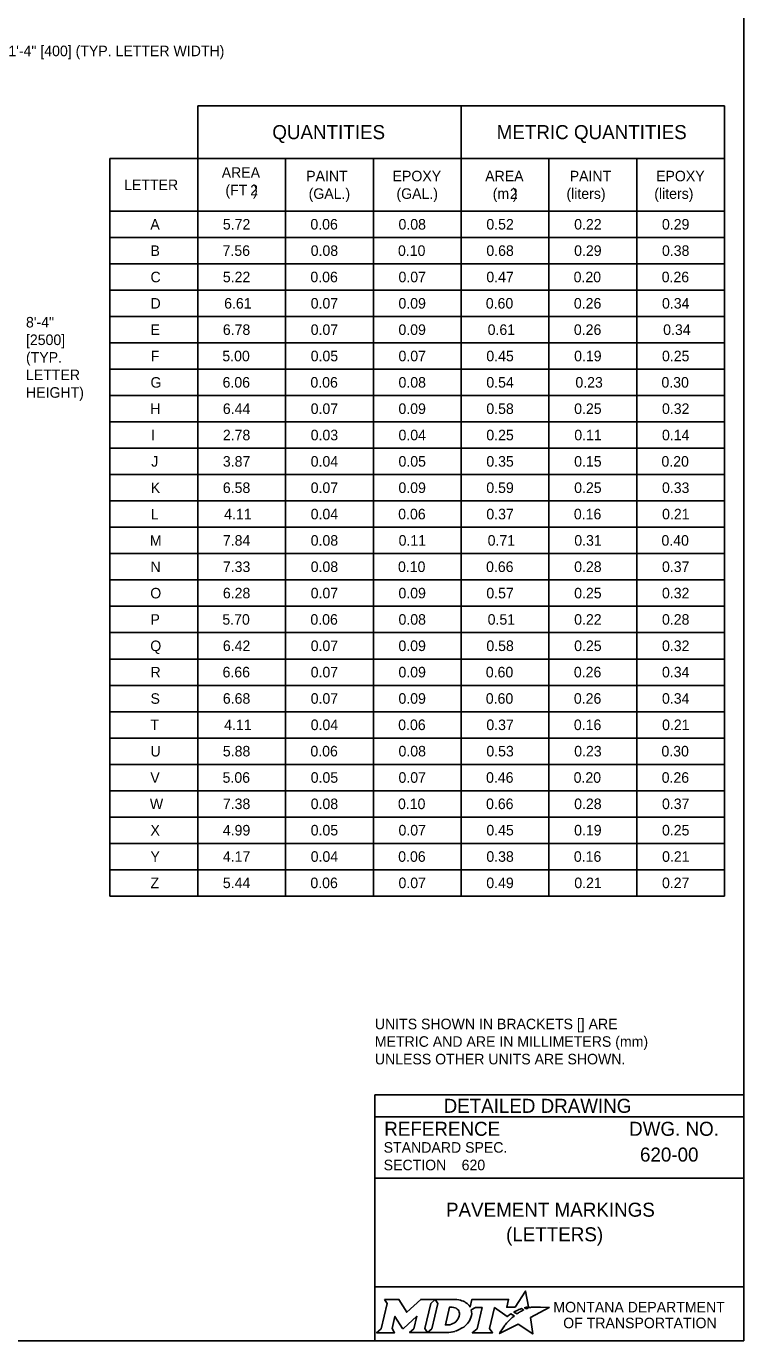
# Model space of a CAD drawing. Extents: x 49991.4 to 50021, y 49987.6 to 50011.4.
# Drawn here: x 50012.67 to 50016.75, y 49987.8 to 49995.28 of the extents above; entities that cross this region are included whole.
import ezdxf

# ---------------------------------------------------------------- set-up
doc = ezdxf.new("R2010")
doc.units = 0
for name, color, linetype in [('Default', 7, 'Continuous'), ('Level 1', 7, 'Continuous'), ('Level 2', 7, 'Continuous'), ('Level 5', 7, 'Continuous')]:
    doc.layers.add(name, color=color, linetype=linetype)

msp = doc.modelspace()

# ---------------------------------------------------------------- linework, layer by layer
at = {"layer": 'Default'}
for points in [[(50015.5126, 49987.9811), (50015.5023, 49987.9867), (50015.5139, 49987.9895), (50015.5255, 49987.9915), (50015.5081, 49988.0816), (50015.4486, 49987.9903), (50015.4013, 49987.9896), (50015.4116, 49988.0337), (50015.2024, 49988.0338), (50015.1923, 49987.9913), (50015.1865, 49987.9996)], [(50014.7056, 49988.0338), (50014.7197, 49988.0104), (50014.6862, 49987.8671), (50014.6605, 49987.8446), (50014.7621, 49987.8446), (50014.7486, 49987.8674), (50014.7648, 49987.9375), (50014.8085, 49987.8685), (50014.8138, 49987.8685), (50014.8889, 49987.938), (50014.8725, 49987.8669), (50014.8478, 49987.8449), (50014.9494, 49987.8449), (50014.9356, 49987.8682), (50014.9688, 49988.0106)], [(50014.9688, 49988.0106), (50014.9941, 49988.0338), (50014.9117, 49988.0338), (50014.8321, 49987.9608), (50014.7876, 49988.0335), (50014.7056, 49988.0338)], [(50015.1077, 49988.0338), (50014.9941, 49988.0338), (50015.0088, 49988.0109), (50014.9749, 49987.8671), (50014.9494, 49987.8449), (50015.06, 49987.8449)], [(50015.3882, 49987.8843), (50015.3729, 49987.8599), (50015.3682, 49987.8524), (50015.3624, 49987.8438), (50015.3601, 49987.8395), (50015.4654, 49987.8926), (50015.5493, 49987.8375), (50015.5362, 49987.9302), (50015.6431, 49987.9886), (50015.5938, 49987.9894), (50015.5637, 49987.9898), (50015.5429, 49987.9901), (50015.5361, 49987.9886), (50015.5312, 49987.9874), (50015.5228, 49987.9851), (50015.5126, 49987.9811)], [(50015.1317, 49987.9471), (50015.1305, 49987.939), (50015.1273, 49987.9297), (50015.1231, 49987.9215), (50015.1175, 49987.914), (50015.111, 49987.9071), (50015.1031, 49987.9008), (50015.0948, 49987.8961), (50015.0857, 49987.8922), (50015.0766, 49987.8899), (50015.0674, 49987.889), (50015.0515, 49987.889), (50015.0751, 49987.989), (50015.0911, 49987.989), (50015.0987, 49987.9884), (50015.1063, 49987.9865), (50015.1129, 49987.9835), (50015.119, 49987.9793), (50015.1238, 49987.9743), (50015.1275, 49987.9683), (50015.1302, 49987.9621), (50015.1318, 49987.9547), (50015.1318, 49987.9517), (50015.1317, 49987.9471)], [(50015.1991, 49987.9747), (50015.2237, 49987.9878), (50015.2606, 49987.9878), (50015.232, 49987.8673), (50015.2045, 49987.8446), (50015.3207, 49987.8446), (50015.3037, 49987.8675), (50015.3319, 49987.9877), (50015.4032, 49987.936), (50015.4243, 49987.9511), (50015.444, 49987.9402)], [(50015.4622, 49987.9535), (50015.4598, 49987.9518), (50015.4415, 49987.9614), (50015.4518, 49987.9671), (50015.4559, 49987.9693), (50015.4645, 49987.9733), (50015.4702, 49987.9759), (50015.4781, 49987.9789), (50015.4854, 49987.9816), (50015.4972, 49987.9742), (50015.4932, 49987.9721), (50015.4886, 49987.9696), (50015.4844, 49987.9674), (50015.4794, 49987.9645), (50015.4775, 49987.9634), (50015.4748, 49987.9618), (50015.4723, 49987.9604), (50015.47, 49987.9588), (50015.4674, 49987.957), (50015.4647, 49987.9552), (50015.4622, 49987.9535)], [(50015.1057, 49987.8522), (50015.1141, 49987.8548), (50015.1271, 49987.8602), (50015.1475, 49987.8712)], [(50015.4021, 49987.9004), (50015.4021, 49987.9004)]]:
    msp.add_lwpolyline(points, dxfattribs=at)
for centre, radius, start, end in [((50015.0868, 49987.9727), 0.1183, 300.91025, 339.13831), ((50015.1308, 49987.9554), 0.0709, 339.53292, 15.85821)]:
    msp.add_arc(centre, radius, start, end, dxfattribs=at)
for centre, major_axis, ratio, start_param, end_param in [((50015.1056, 49987.9864), (0.0834, -0.0037), 0.568097, 0.61298, 1.570796), ((50015.1612, 49987.9937), (0.0361, -0.0295), 0.469099, 1.225588, 1.570796), ((50015.4119, 49987.9106), (-0.0098, -0.0102), 0.016458, 3.141593, 6.279097), ((50015.4329, 49987.9305), (-0.0112, -0.0097), 0.021651, 3.157348, 6.283185), ((50015.0603, 49987.9932), (0, 0.1484), 0.987302, 3.139398, 3.456847), ((50015.3952, 49987.8923), (-0.00694, -0.00806), 0.008222, 0, 3.137361)]:
    msp.add_ellipse(centre, major_axis=major_axis, ratio=ratio, start_param=start_param, end_param=end_param, dxfattribs=at)
at = {"layer": 'Level 1'}
msp.add_lwpolyline([(49999.3835, 49998.9992), (50016.7501, 49998.9992), (50016.7501, 49987.7988), (49999.3835, 49987.7988)], close=True, dxfattribs=at)
at = {"layer": 'Level 2'}
for p, q in [((50013.6416, 49994.8304), (50013.6416, 49990.3304)), ((50013.6416, 49994.8304), (50016.6416, 49994.8304)), ((50015.1416, 49994.8304), (50015.1416, 49990.3304)), ((50016.6416, 49994.8304), (50016.6416, 49990.3304)), ((50013.1416, 49994.5304), (50016.6416, 49994.5304)), ((50013.1416, 49994.5304), (50013.1416, 49990.3304)), ((50014.1416, 49994.5304), (50014.1416, 49990.3304)), ((50014.6416, 49994.5304), (50014.6416, 49990.3304)), ((50015.6416, 49994.5304), (50015.6416, 49990.3304)), ((50016.1416, 49994.5304), (50016.1416, 49990.3304)), ((50013.1416, 49994.2304), (50016.6416, 49994.2304)), ((50013.1416, 49994.0804), (50016.6416, 49994.0804)), ((50013.1416, 49993.9304), (50016.6416, 49993.9304)), ((50013.1416, 49993.7804), (50016.6416, 49993.7804)), ((50013.1416, 49993.6304), (50016.6416, 49993.6304)), ((50013.1416, 49993.4804), (50016.6416, 49993.4804)), ((50013.1416, 49993.3304), (50016.6416, 49993.3304)), ((50013.1416, 49993.1804), (50016.6416, 49993.1804)), ((50013.1416, 49993.0304), (50016.6416, 49993.0304)), ((50013.1416, 49992.8804), (50016.6416, 49992.8804)), ((50013.1416, 49992.7304), (50016.6416, 49992.7304)), ((50013.1416, 49992.5804), (50016.6416, 49992.5804)), ((50013.1416, 49992.4304), (50016.6416, 49992.4304)), ((50013.1416, 49992.2804), (50016.6416, 49992.2804)), ((50013.1416, 49992.1304), (50016.6416, 49992.1304)), ((50013.1416, 49991.9804), (50016.6416, 49991.9804)), ((50013.1416, 49991.8304), (50016.6416, 49991.8304)), ((50013.1416, 49991.6804), (50016.6416, 49991.6804)), ((50013.1416, 49991.5304), (50016.6416, 49991.5304)), ((50013.1416, 49991.3804), (50016.6416, 49991.3804)), ((50013.1416, 49991.2304), (50016.6416, 49991.2304)), ((50013.1416, 49991.0804), (50016.6416, 49991.0804)), ((50013.1416, 49990.9304), (50016.6416, 49990.9304)), ((50013.1416, 49990.7804), (50016.6416, 49990.7804)), ((50013.1416, 49990.6304), (50016.6416, 49990.6304)), ((50013.1416, 49990.4804), (50016.6416, 49990.4804)), ((50013.1416, 49990.3304), (50016.6416, 49990.3304))]:
    msp.add_line(p, q, dxfattribs=at)
at = {"layer": 'Level 5'}
for p, q in [((50016.7501, 49989.1988), (50014.6501, 49989.1988)), ((50014.6501, 49989.1988), (50014.6501, 49987.7988)), ((50016.7501, 49989.0738), (50014.6501, 49989.0738)), ((50016.3862, 49988.8587), (50016.3862, 49988.8587)), ((50015.1444, 49988.7993), (50015.1444, 49988.7993)), ((50016.7501, 49988.7238), (50014.6501, 49988.7238)), ((50015.7001, 49988.4747), (50015.7001, 49988.4747)), ((50016.7501, 49988.1057), (50014.6501, 49988.1057))]:
    msp.add_line(p, q, dxfattribs=at)

# ---------------------------------------------------------------- texts
at = {"layer": 'Default'}
for s, p in [('MONTANA DEPARTMENT', (50015.6663, 49987.96)), ('OF TRANSPORTATION', (50015.7225, 49987.87))]:
    msp.add_text(s, height=0.06, dxfattribs=at).set_placement(p)
at = {"layer": 'Level 2'}
for s, height, p in [('1\'-4" [400] (TYP. LETTER WIDTH)', 0.06, (50012.5638, 49995.1128)), ('QUANTITIES', 0.08, (50014.0664, 49994.6404)), ('METRIC QUANTITIES', 0.08, (50015.3439, 49994.6404)), ('AREA', 0.06, (50013.7783, 49994.4204)), ('PAINT', 0.06, (50014.2595, 49994.4004)), ('EPOXY', 0.06, (50014.7513, 49994.4004)), ('AREA', 0.06, (50015.2783, 49994.4004)), ('PAINT', 0.06, (50015.7595, 49994.4004)), ('EPOXY', 0.06, (50016.2513, 49994.4004)), ('LETTER', 0.06, (50013.223, 49994.3504)), ('(FT', 0.06, (50013.7995, 49994.3204)), ('2', 0.06, (50013.9405, 49994.3204)), (')', 0.06, (50013.9567, 49994.3204)), ('(GAL.)', 0.06, (50014.2732, 49994.3004)), ('(GAL.)', 0.06, (50014.7732, 49994.3004)), ('(m', 0.06, (50015.3211, 49994.3004)), ('2', 0.06, (50015.4189, 49994.3004)), (')', 0.06, (50015.4351, 49994.3004)), ('(liters)', 0.06, (50015.741, 49994.3004)), ('(liters)', 0.06, (50016.241, 49994.3004)), ('A', 0.06, (50013.372, 49994.1254)), ('5.72', 0.06, (50013.785, 49994.1257)), ('0.06', 0.06, (50014.2833, 49994.1257)), ('0.08', 0.06, (50014.7849, 49994.1257)), ('0.52', 0.06, (50015.285, 49994.1257)), ('0.22', 0.06, (50015.785, 49994.1257)), ('0.29', 0.06, (50016.2847, 49994.1257)), ('B', 0.06, (50013.373, 49993.9754)), ('7.56', 0.06, (50013.7834, 49993.9757)), ('0.08', 0.06, (50014.285, 49993.9757)), ('0.10', 0.06, (50014.7819, 49993.9757)), ('0.68', 0.06, (50015.285, 49993.9757)), ('0.29', 0.06, (50015.7848, 49993.9757)), ('0.38', 0.06, (50016.2849, 49993.9757)), ('C', 0.06, (50013.373, 49993.8254)), ('5.22', 0.06, (50013.7849, 49993.8257)), ('0.06', 0.06, (50014.2833, 49993.8257)), ('0.07', 0.06, (50014.7849, 49993.8257)), ('0.47', 0.06, (50015.285, 49993.8257)), ('0.20', 0.06, (50015.7819, 49993.8257)), ('0.26', 0.06, (50016.2832, 49993.8257)), ('D', 0.06, (50013.373, 49993.6754)), ('6.61', 0.06, (50013.7923, 49993.6757)), ('0.07', 0.06, (50014.285, 49993.6757)), ('0.09', 0.06, (50014.7846, 49993.6757)), ('0.60', 0.06, (50015.282, 49993.6757)), ('0.26', 0.06, (50015.7833, 49993.6757)), ('0.34', 0.06, (50016.285, 49993.6757)), ('8\'-4"', 0.06, (50012.6641, 49993.5681)), ('[2500]', 0.06, (50012.6641, 49993.4681)), ('E', 0.06, (50013.3732, 49993.5254)), ('6.78', 0.06, (50013.785, 49993.5257)), ('0.07', 0.06, (50014.285, 49993.5257)), ('0.09', 0.06, (50014.7846, 49993.5257)), ('0.61', 0.06, (50015.2924, 49993.5257)), ('0.26', 0.06, (50015.7833, 49993.5257)), ('0.34', 0.06, (50016.2917, 49993.5257)), ('(TYP.', 0.06, (50012.6641, 49993.3681)), ('F', 0.06, (50013.3744, 49993.3754)), ('5.00', 0.06, (50013.782, 49993.3757)), ('0.05', 0.06, (50014.285, 49993.3757)), ('0.07', 0.06, (50014.7849, 49993.3757)), ('0.45', 0.06, (50015.285, 49993.3757)), ('0.19', 0.06, (50015.7847, 49993.3757)), ('0.25', 0.06, (50016.2849, 49993.3757)), ('LETTER ', 0.06, (50012.6641, 49993.2681)), ('HEIGHT)', 0.06, (50012.6641, 49993.1681)), ('G', 0.06, (50013.373, 49993.2254)), ('6.06', 0.06, (50013.7833, 49993.2257)), ('0.06', 0.06, (50014.2834, 49993.2257)), ('0.08', 0.06, (50014.7849, 49993.2257)), ('0.54', 0.06, (50015.285, 49993.2257)), ('0.23', 0.06, (50015.7918, 49993.2257)), ('0.30', 0.06, (50016.2818, 49993.2257)), ('H', 0.06, (50013.372, 49993.0754)), ('6.44', 0.06, (50013.785, 49993.0757)), ('0.07', 0.06, (50014.285, 49993.0757)), ('0.09', 0.06, (50014.7846, 49993.0757)), ('0.58', 0.06, (50015.285, 49993.0757)), ('0.25', 0.06, (50015.785, 49993.0757)), ('0.32', 0.06, (50016.2849, 49993.0757)), ('I', 0.06, (50013.3766, 49992.9254)), ('2.78', 0.06, (50013.785, 49992.9257)), ('0.03', 0.06, (50014.285, 49992.9257)), ('0.04', 0.06, (50014.7849, 49992.9257)), ('0.25', 0.06, (50015.285, 49992.9257)), ('0.11', 0.06, (50015.7856, 49992.9257)), ('0.14', 0.06, (50016.2849, 49992.9257)), ('J', 0.06, (50013.3768, 49992.7754)), ('3.87', 0.06, (50013.785, 49992.7757)), ('0.04', 0.06, (50014.285, 49992.7757)), ('0.05', 0.06, (50014.7849, 49992.7757)), ('0.35', 0.06, (50015.285, 49992.7757)), ('0.15', 0.06, (50015.785, 49992.7757)), ('0.20', 0.06, (50016.2818, 49992.7757)), ('K', 0.06, (50013.3746, 49992.6254)), ('6.58', 0.06, (50013.785, 49992.6257)), ('0.07', 0.06, (50014.285, 49992.6257)), ('0.09', 0.06, (50014.7846, 49992.6257)), ('0.59', 0.06, (50015.2848, 49992.6257)), ('0.25', 0.06, (50015.785, 49992.6257)), ('0.33', 0.06, (50016.2849, 49992.6257)), ('L', 0.06, (50013.3746, 49992.4754)), ('4.11', 0.06, (50013.7924, 49992.4757)), ('0.04', 0.06, (50014.285, 49992.4757)), ('0.06', 0.06, (50014.7832, 49992.4757)), ('0.37', 0.06, (50015.285, 49992.4757)), ('0.16', 0.06, (50015.7833, 49992.4757)), ('0.21', 0.06, (50016.2855, 49992.4757)), ('M', 0.06, (50013.3694, 49992.3254)), ('7.84', 0.06, (50013.785, 49992.3257)), ('0.08', 0.06, (50014.285, 49992.3257)), ('0.11', 0.06, (50014.7855, 49992.3257)), ('0.71', 0.06, (50015.2924, 49992.3257)), ('0.31', 0.06, (50015.7856, 49992.3257)), ('0.40', 0.06, (50016.2819, 49992.3257)), ('N', 0.06, (50013.373, 49992.1754)), ('7.33', 0.06, (50013.785, 49992.1757)), ('0.08', 0.06, (50014.285, 49992.1757)), ('0.10', 0.06, (50014.7819, 49992.1757)), ('0.66', 0.06, (50015.2834, 49992.1757)), ('0.28', 0.06, (50015.785, 49992.1757)), ('0.37', 0.06, (50016.2849, 49992.1757)), ('O', 0.06, (50013.3718, 49992.0254)), ('6.28', 0.06, (50013.7851, 49992.0257)), ('0.07', 0.06, (50014.285, 49992.0257)), ('0.09', 0.06, (50014.7846, 49992.0257)), ('0.57', 0.06, (50015.285, 49992.0257)), ('0.25', 0.06, (50015.785, 49992.0257)), ('0.32', 0.06, (50016.2848, 49992.0257)), ('P', 0.06, (50013.373, 49991.8754)), ('5.70', 0.06, (50013.7821, 49991.8757)), ('0.06', 0.06, (50014.2833, 49991.8757)), ('0.08', 0.06, (50014.7849, 49991.8757)), ('0.51', 0.06, (50015.2924, 49991.8757)), ('0.22', 0.06, (50015.785, 49991.8757)), ('0.28', 0.06, (50016.2849, 49991.8757)), ('Q', 0.06, (50013.3718, 49991.7254)), ('6.42', 0.06, (50013.785, 49991.7257)), ('0.07', 0.06, (50014.285, 49991.7257)), ('0.09', 0.06, (50014.7846, 49991.7257)), ('0.58', 0.06, (50015.2851, 49991.7257)), ('0.25', 0.06, (50015.785, 49991.7257)), ('0.32', 0.06, (50016.285, 49991.7257)), ('R', 0.06, (50013.373, 49991.5754)), ('6.66', 0.06, (50013.7833, 49991.5757)), ('0.07', 0.06, (50014.285, 49991.5757)), ('0.09', 0.06, (50014.7846, 49991.5757)), ('0.60', 0.06, (50015.282, 49991.5757)), ('0.26', 0.06, (50015.7833, 49991.5757)), ('0.34', 0.06, (50016.2849, 49991.5757)), ('S', 0.06, (50013.3732, 49991.4254)), ('6.68', 0.06, (50013.785, 49991.4257)), ('0.07', 0.06, (50014.285, 49991.4257)), ('0.09', 0.06, (50014.7846, 49991.4257)), ('0.60', 0.06, (50015.282, 49991.4257)), ('0.26', 0.06, (50015.7833, 49991.4257)), ('0.34', 0.06, (50016.2849, 49991.4257)), ('T', 0.06, (50013.372, 49991.2754)), ('4.11', 0.06, (50013.7924, 49991.2757)), ('0.04', 0.06, (50014.285, 49991.2757)), ('0.06', 0.06, (50014.7832, 49991.2757)), ('0.37', 0.06, (50015.285, 49991.2757)), ('0.16', 0.06, (50015.7833, 49991.2757)), ('0.21', 0.06, (50016.2855, 49991.2757)), ('U', 0.06, (50013.3728, 49991.1254)), ('5.88', 0.06, (50013.785, 49991.1257)), ('0.06', 0.06, (50014.2834, 49991.1257)), ('0.08', 0.06, (50014.7849, 49991.1257)), ('0.53', 0.06, (50015.285, 49991.1257)), ('0.23', 0.06, (50015.7852, 49991.1257)), ('0.30', 0.06, (50016.2818, 49991.1257)), ('V', 0.06, (50013.372, 49990.9754)), ('5.06', 0.06, (50013.7834, 49990.9757)), ('0.05', 0.06, (50014.285, 49990.9757)), ('0.07', 0.06, (50014.7849, 49990.9757)), ('0.46', 0.06, (50015.2834, 49990.9757)), ('0.20', 0.06, (50015.7819, 49990.9757)), ('0.26', 0.06, (50016.2832, 49990.9757)), ('W', 0.06, (50013.3694, 49990.8254)), ('7.38', 0.06, (50013.785, 49990.8257)), ('0.08', 0.06, (50014.285, 49990.8257)), ('0.10', 0.06, (50014.7819, 49990.8257)), ('0.66', 0.06, (50015.2834, 49990.8257)), ('0.28', 0.06, (50015.785, 49990.8257)), ('0.37', 0.06, (50016.2849, 49990.8257)), ('X', 0.06, (50013.3728, 49990.6754)), ('4.99', 0.06, (50013.7848, 49990.6757)), ('0.05', 0.06, (50014.285, 49990.6757)), ('0.07', 0.06, (50014.7849, 49990.6757)), ('0.45', 0.06, (50015.285, 49990.6757)), ('0.19', 0.06, (50015.7847, 49990.6757)), ('0.25', 0.06, (50016.2849, 49990.6757)), ('Y', 0.06, (50013.3728, 49990.5254)), ('4.17', 0.06, (50013.785, 49990.5257)), ('0.04', 0.06, (50014.285, 49990.5257)), ('0.06', 0.06, (50014.7832, 49990.5257)), ('0.38', 0.06, (50015.285, 49990.5257)), ('0.16', 0.06, (50015.7833, 49990.5257)), ('0.21', 0.06, (50016.2855, 49990.5257)), ('Z', 0.06, (50013.373, 49990.3754)), ('5.44', 0.06, (50013.785, 49990.3757)), ('0.06', 0.06, (50014.2833, 49990.3757)), ('0.07', 0.06, (50014.7849, 49990.3757)), ('0.49', 0.06, (50015.2848, 49990.3757)), ('0.21', 0.06, (50015.7856, 49990.3757)), ('0.27', 0.06, (50016.2849, 49990.3757)), ('UNITS SHOWN IN BRACKETS [] ARE ', 0.06, (50014.6501, 49989.5723)), ('METRIC AND ARE IN MILLIMETERS (mm) ', 0.06, (50014.6501, 49989.4723)), ('UNLESS OTHER UNITS ARE SHOWN.', 0.06, (50014.6501, 49989.3723)), ('620-00', 0.08, (50016.1596, 49988.8187)), ('620', 0.06, (50015.1444, 49988.7693)), ('PAVEMENT MARKINGS', 0.08, (50015.0552, 49988.5047)), ('(LETTERS)', 0.08, (50015.3971, 49988.3647))]:
    msp.add_text(s, height=height, dxfattribs=at).set_placement(p)
at = {"layer": 'Level 5'}
for s, height, p in [('DETAILED DRAWING', 0.0799, (50015.0418, 49989.0963)), ('REFERENCE', 0.08, (50014.7037, 49988.9654)), ('DWG. NO.', 0.08, (50016.0979, 49988.9654)), ('STANDARD SPEC.', 0.06, (50014.7004, 49988.8694)), ('SECTION', 0.06, (50014.7004, 49988.7694))]:
    msp.add_text(s, height=height, dxfattribs=at).set_placement(p)

doc.saveas('drawing.dxf')
